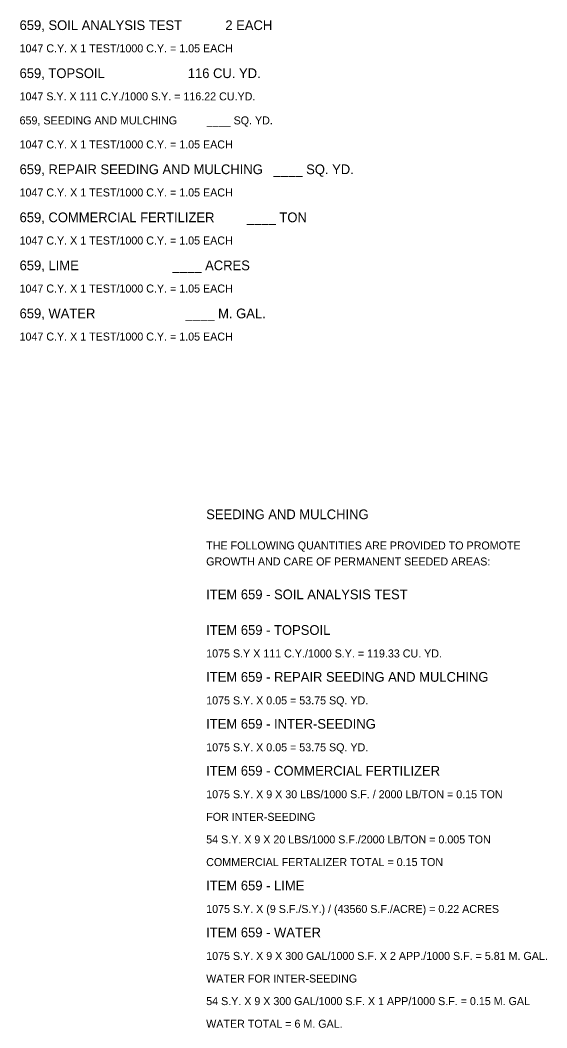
# Model space of a CAD drawing. Extents: x -286 to 93, y -30 to 99.
# Drawn here: x 38.57 to 47.79, y 4.44 to 22.06 of the extents above; entities that cross this region are included whole.
import ezdxf

# ---------------------------------------------------------------- set-up
doc = ezdxf.new("R2010")
doc.units = 0
doc.layers.add('SH_Text', color=7, linetype='Continuous')

msp = doc.modelspace()

# ---------------------------------------------------------------- texts
at = {"layer": 'SH_Text'}
for s, height, p in [('659, SOIL ANALYSIS TEST            2 EACH', 0.17, (38.562, 21.885)), ('1047 C.Y. X 1 TEST/1000 C.Y. = 1.05 EACH', 0.14, (38.562, 21.495)), ('659, TOPSOIL                       116 CU. YD.', 0.17, (38.562, 21.045)), ('1047 S.Y. X 111 C.Y./1000 S.Y. = 116.22 CU.YD.', 0.14, (38.562, 20.655)), ('659, SEEDING AND MULCHING          ____ SQ. YD.', 0.14, (38.562, 20.235)), ('1047 C.Y. X 1 TEST/1000 C.Y. = 1.05 EACH', 0.14, (38.562, 19.815)), ('659, REPAIR SEEDING AND MULCHING   ____ SQ. YD.', 0.17, (38.562, 19.365)), ('1047 C.Y. X 1 TEST/1000 C.Y. = 1.05 EACH', 0.14, (38.562, 18.975)), ('659, COMMERCIAL FERTILIZER         ____ TON', 0.17, (38.562, 18.525)), ('1047 C.Y. X 1 TEST/1000 C.Y. = 1.05 EACH', 0.14, (38.562, 18.135)), ('659, LIME                          ____ ACRES', 0.17, (38.562, 17.685)), ('1047 C.Y. X 1 TEST/1000 C.Y. = 1.05 EACH', 0.14, (38.562, 17.295)), ('659, WATER                         ____ M. GAL.', 0.17, (38.562, 16.845)), ('1047 C.Y. X 1 TEST/1000 C.Y. = 1.05 EACH', 0.14, (38.562, 16.455)), ('SEEDING AND MULCHING', 0.17, (41.828, 13.332)), ('THE FOLLOWING QUANTITIES ARE PROVIDED TO PROMOTE', 0.14, (41.828, 12.802)), ('GROWTH AND CARE OF PERMANENT SEEDED AREAS:', 0.14, (41.828, 12.522)), ('ITEM 659 - SOIL ANALYSIS TEST', 0.17, (41.828, 11.932)), ('ITEM 659 - TOPSOIL', 0.17, (41.828, 11.309)), ('1075 S.Y X 111 C.Y./1000 S.Y. = 119.33 CU. YD.', 0.14, (41.828, 10.914)), ('ITEM 659 - REPAIR SEEDING AND MULCHING', 0.17, (41.828, 10.489)), ('1075 S.Y. X 0.05 = 53.75 SQ. YD.           ', 0.14, (41.828, 10.093)), ('ITEM 659 - INTER-SEEDING', 0.17, (41.828, 9.668)), ('1075 S.Y. X 0.05 = 53.75 SQ. YD.                                                          ', 0.14, (41.828, 9.273)), ('ITEM 659 - COMMERCIAL FERTILIZER', 0.17, (41.828, 8.848)), ('1075 S.Y. X 9 X 30 LBS/1000 S.F. / 2000 LB/TON = 0.15 TON', 0.14, (41.828, 8.452)), ('FOR INTER-SEEDING', 0.14, (41.828, 8.057)), ('54 S.Y. X 9 X 20 LBS/1000 S.F./2000 LB/TON = 0.005 TON', 0.14, (41.828, 7.662)), ('COMMERCIAL FERTALIZER TOTAL = 0.15 TON  ', 0.14, (41.828, 7.266)), ('ITEM 659 - LIME', 0.17, (41.828, 6.841)), ('1075 S.Y. X (9 S.F./S.Y.) / (43560 S.F./ACRE) = 0.22 ACRES', 0.14, (41.828, 6.446)), ('ITEM 659 - WATER', 0.17, (41.828, 6.021)), ('1075 S.Y. X 9 X 300 GAL/1000 S.F. X 2 APP./1000 S.F. = 5.81 M. GAL.  ', 0.14, (41.828, 5.625)), ('WATER FOR INTER-SEEDING', 0.14, (41.828, 5.23)), ('54 S.Y. X 9 X 300 GAL/1000 S.F. X 1 APP/1000 S.F. = 0.15 M. GAL', 0.14, (41.828, 4.835)), ('WATER TOTAL = 6 M. GAL.  ', 0.14, (41.828, 4.439))]:
    msp.add_text(s, height=height, dxfattribs=at).set_placement(p)

doc.saveas('drawing.dxf')
